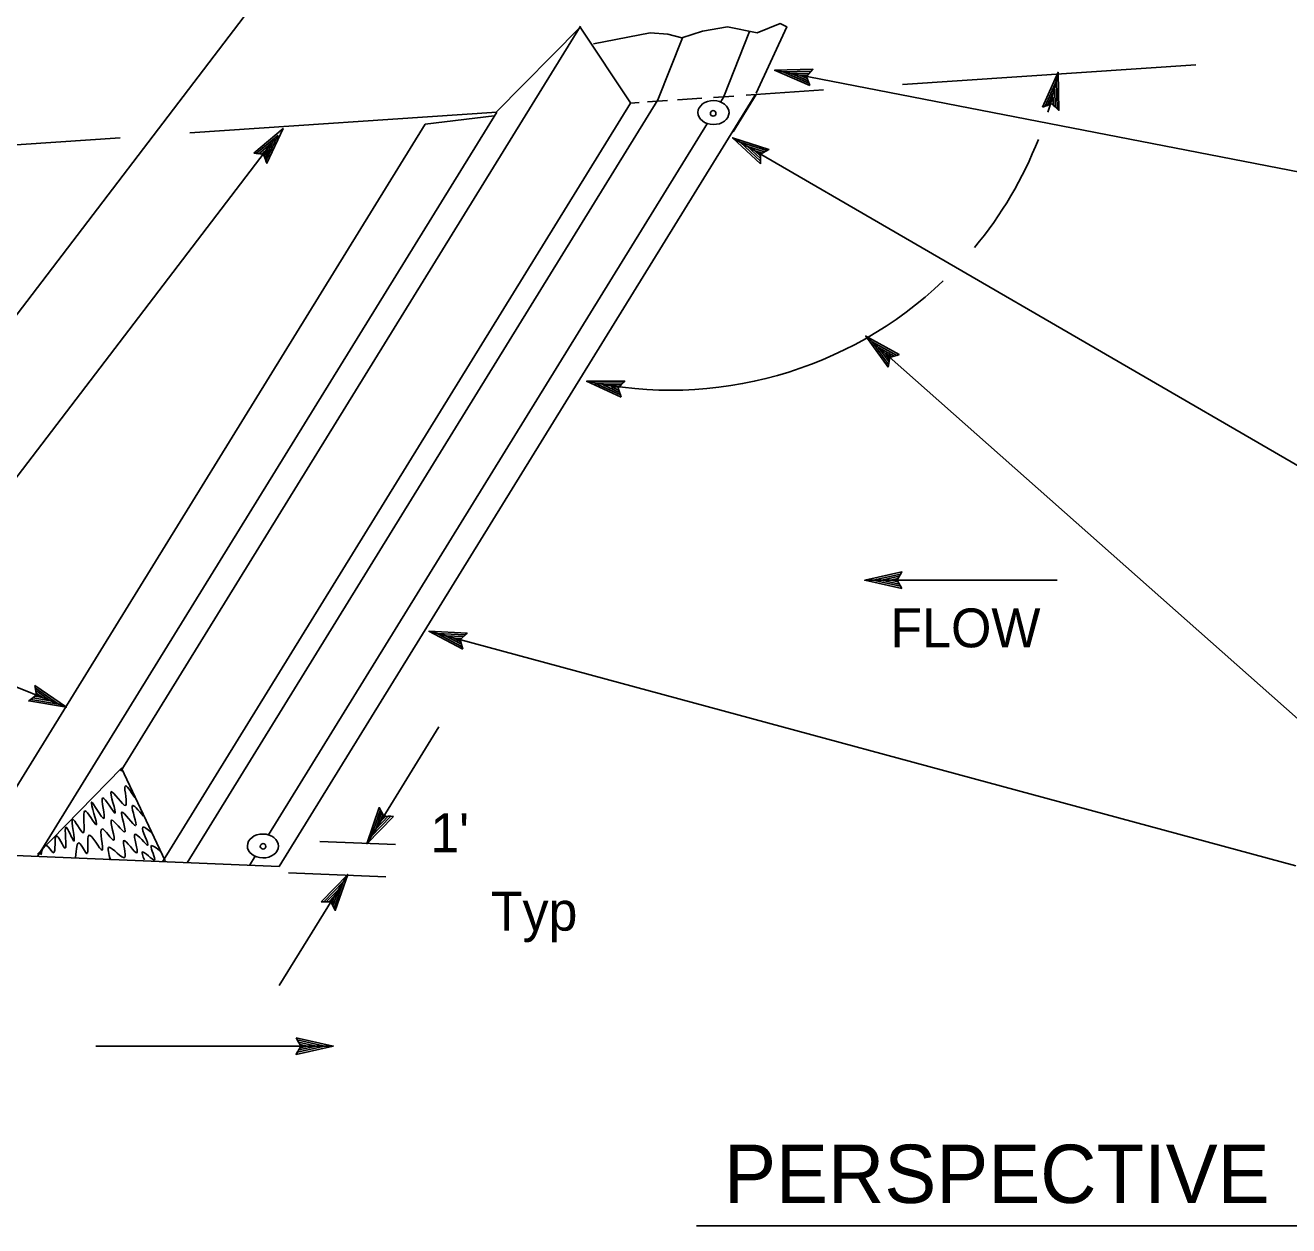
# Model space of a CAD drawing. Extents: x 6708945 to 6710368, y 1871409 to 1872338.
# Drawn here: x 6709648 to 6709843.2, y 1871758.9 to 1871944.4 of the extents above; entities that cross this region are included whole.
import ezdxf

# ---------------------------------------------------------------- set-up
doc = ezdxf.new("R2010")
doc.units = 0
doc.layers.add('57 Undefined', color=7, linetype='Continuous')
doc.layers.add('60 Nongeo Data', color=7, linetype='Continuous')

msp = doc.modelspace()

# ---------------------------------------------------------------- linework, layer by layer
at = {"layer": '57 Undefined'}
for p, q in [((6709642.88, 1871894.69), (6709692.17, 1871959.27)), ((6709763.76, 1871937.4), (6709845.14, 1871921.6)), ((6709646.09, 1871873.81), (6709686.54, 1871926.81)), ((6709757.25, 1871926.98), (6709845.14, 1871876)), ((6709777.83, 1871896.35), (6709846.44, 1871835.61)), ((6709777.67, 1871858.65), (6709807.39, 1871858.65)), ((6709626.36, 1871850.36), (6709654.36, 1871839.02)), ((6709710.36, 1871850.75), (6709844.26, 1871814.52)), ((6709700.75, 1871817.95), (6709711.89, 1871836.01)), ((6709687.23, 1871796.04), (6709697.83, 1871813.21)), ((6709695.59, 1871786.69), (6709658.88, 1871786.69)), ((6709751.68, 1871758.94), (6709848.82, 1871758.94))]:
    msp.add_line(p, q, dxfattribs=at)
for points in [[(6709693.49, 1871818.31), (6709705.21, 1871817.82)], [(6709688.65, 1871813.47), (6709703.71, 1871812.85)]]:
    msp.add_lwpolyline(points, dxfattribs=at)
for start, end in [(342.7521, 348.7024), (320.2883, 338.553), (257.7557, 313.6577)]:
    msp.add_arc((6709747.65, 1871949.07), 61.08, start, end, dxfattribs=at)
at = {"layer": '60 Nongeo Data'}
for p, q in [((6709662.75, 1871829.15), (6709733.77, 1871944.23)), ((6709745.71, 1871932.83), (6709749.51, 1871942.44)), ((6709755.93, 1871933.37), (6709759.89, 1871943.38)), ((6709763.76, 1871937.4), (6709763.76, 1871937.4)), ((6709769.66, 1871937.56), (6709769.66, 1871937.56)), ((6709807.55, 1871937.1), (6709807.55, 1871937.1)), ((6709769.17, 1871935.04), (6709769.17, 1871935.04)), ((6709669.18, 1871815.17), (6709741.49, 1871932.34)), ((6709672.99, 1871815.01), (6709745.71, 1871932.83)), ((6709687.23, 1871814.41), (6709760.72, 1871933.5)), ((6709755.42, 1871932.5), (6709755.92, 1871933.32)), ((6709757.34, 1871927.92), (6709760.88, 1871933.66)), ((6709649.88, 1871815.97), (6709720.83, 1871930.94)), ((6709709.77, 1871929.07), (6709720.41, 1871930.37)), ((6709805.16, 1871931.71), (6709805.16, 1871931.71)), ((6709807.68, 1871931.2), (6709807.68, 1871931.2)), ((6709640.23, 1871816.37), (6709709.77, 1871929.07)), ((6709685.57, 1871819.32), (6709753.41, 1871929.25)), ((6709687.82, 1871928.41), (6709687.82, 1871928.41)), ((6709757.25, 1871926.98), (6709757.25, 1871926.98)), ((6709683.3, 1871924.61), (6709683.3, 1871924.61)), ((6709762.88, 1871925.19), (6709762.88, 1871925.19)), ((6709685.34, 1871923.05), (6709685.34, 1871923.05)), ((6709761.59, 1871922.97), (6709761.59, 1871922.97)), ((6709777.83, 1871896.35), (6709777.83, 1871896.35)), ((6709782.99, 1871893.49), (6709782.99, 1871893.49)), ((6709781.29, 1871891.57), (6709781.29, 1871891.57)), ((6709734.7, 1871889.37), (6709734.7, 1871889.37)), ((6709740.6, 1871889.4), (6709740.6, 1871889.4)), ((6709740.05, 1871886.9), (6709740.05, 1871886.9)), ((6709783.43, 1871859.93), (6709783.43, 1871859.93)), ((6709777.67, 1871858.65), (6709777.67, 1871858.65)), ((6709783.43, 1871857.37), (6709783.43, 1871857.37)), ((6709710.36, 1871850.75), (6709710.36, 1871850.75)), ((6709716.26, 1871850.48), (6709716.26, 1871850.48)), ((6709715.59, 1871848), (6709715.59, 1871848)), ((6709649.5, 1871842.38), (6709649.5, 1871842.38)), ((6709648.54, 1871840), (6709648.54, 1871840)), ((6709654.36, 1871839.02), (6709654.36, 1871839.02)), ((6709702.69, 1871823.52), (6709702.69, 1871823.52)), ((6709704.87, 1871822.17), (6709704.87, 1871822.17)), ((6709700.75, 1871817.95), (6709700.75, 1871817.95)), ((6709682.66, 1871814.6), (6709683.53, 1871816.02)), ((6709697.83, 1871813.21), (6709697.83, 1871813.21)), ((6709693.71, 1871808.98), (6709693.71, 1871808.98)), ((6709695.89, 1871807.64), (6709695.89, 1871807.64)), ((6709689.83, 1871787.98), (6709689.83, 1871787.98)), ((6709695.59, 1871786.69), (6709695.59, 1871786.69)), ((6709689.83, 1871785.42), (6709689.83, 1871785.42))]:
    msp.add_line(p, q, dxfattribs=at)
for points in [[(6709720.68, 1871930.86), (6709733.7, 1871944.08), (6709741.48, 1871932.4)], [(6709735.78, 1871941.5), (6709744.54, 1871943.18), (6709747.24, 1871942.97), (6709749.4, 1871942.44), (6709752.63, 1871943.46), (6709756.46, 1871944.11), (6709761.04, 1871943.21), (6709764.6, 1871944.61), (6709765.62, 1871944.13), (6709760.91, 1871933.87)], [(6709783.5, 1871935.19), (6709828.82, 1871938.27)], [(6709759.35, 1871933.55), (6709771.31, 1871934.36)], [(6709741.49, 1871932.34), (6709742.82, 1871932.43)], [(6709744.14, 1871932.52), (6709747.22, 1871932.73)], [(6709748.76, 1871932.83), (6709752.52, 1871933.09)], [(6709754.3, 1871933.21), (6709757.48, 1871933.43)], [(6709673.41, 1871927.72), (6709720.83, 1871930.94)], [(6709628.22, 1871924.65), (6709662.68, 1871926.99)], [(6709649.92, 1871816.31), (6709662.86, 1871829.62), (6709669.63, 1871815.28)], [(6709640.23, 1871816.37), (6709687.23, 1871814.41)]]:
    msp.add_lwpolyline(points, dxfattribs=at)
for points in [[(6709769.17, 1871935.04), (6709763.76, 1871937.4), (6709769.66, 1871937.56), (6709769.4, 1871937.26), (6709765.08, 1871937.15), (6709769.04, 1871935.41), (6709768.9, 1871935.79), (6709766.37, 1871936.89), (6709769.13, 1871936.97), (6709768.86, 1871936.67), (6709767.67, 1871936.64), (6709768.77, 1871936.16), (6709768.66, 1871936.45), (6709769.66, 1871937.56), (6709768.66, 1871936.45)], [(6709805.16, 1871931.71), (6709807.55, 1871937.1), (6709807.68, 1871931.2), (6709807.38, 1871931.47), (6709807.29, 1871935.79), (6709805.54, 1871931.84), (6709805.91, 1871931.97), (6709807.03, 1871934.5), (6709807.09, 1871931.74), (6709806.8, 1871932.01), (6709806.77, 1871933.2), (6709806.28, 1871932.1), (6709806.57, 1871932.21), (6709807.68, 1871931.2), (6709806.57, 1871932.21)], [(6709683.3, 1871924.61), (6709687.82, 1871928.41), (6709685.34, 1871923.05), (6709685.19, 1871923.42), (6709687.01, 1871927.34), (6709683.69, 1871924.56), (6709684.09, 1871924.52), (6709686.21, 1871926.3), (6709685.04, 1871923.79), (6709684.9, 1871924.16), (6709685.4, 1871925.24), (6709684.48, 1871924.47), (6709684.79, 1871924.44), (6709685.34, 1871923.05), (6709684.79, 1871924.44)], [(6709761.59, 1871922.97), (6709757.25, 1871926.98), (6709762.88, 1871925.19), (6709762.53, 1871925), (6709758.41, 1871926.31), (6709761.58, 1871923.37), (6709761.58, 1871923.77), (6709759.55, 1871925.64), (6709762.18, 1871924.81), (6709761.83, 1871924.62), (6709760.69, 1871924.98), (6709761.57, 1871924.16), (6709761.57, 1871924.47), (6709762.88, 1871925.19), (6709761.57, 1871924.47)], [(6709781.29, 1871891.57), (6709777.83, 1871896.35), (6709782.99, 1871893.49), (6709782.61, 1871893.37), (6709778.83, 1871895.47), (6709781.36, 1871891.96), (6709781.44, 1871892.35), (6709779.82, 1871894.59), (6709782.23, 1871893.25), (6709781.85, 1871893.13), (6709780.81, 1871893.71), (6709781.51, 1871892.74), (6709781.57, 1871893.05), (6709782.99, 1871893.49), (6709781.57, 1871893.05)], [(6709740.05, 1871886.9), (6709734.7, 1871889.37), (6709740.6, 1871889.4), (6709740.32, 1871889.11), (6709736, 1871889.09), (6709739.93, 1871887.27), (6709739.8, 1871887.65), (6709737.29, 1871888.81), (6709740.05, 1871888.82), (6709739.78, 1871888.53), (6709738.58, 1871888.53), (6709739.67, 1871888.02), (6709739.58, 1871888.32), (6709740.6, 1871889.4), (6709739.58, 1871888.32)], [(6709783.43, 1871857.37), (6709777.67, 1871858.65), (6709783.43, 1871859.93), (6709783.22, 1871859.59), (6709779, 1871858.66), (6709783.22, 1871857.71), (6709783.02, 1871858.05), (6709780.32, 1871858.65), (6709783.02, 1871859.25), (6709782.81, 1871858.91), (6709781.65, 1871858.65), (6709782.82, 1871858.39), (6709782.66, 1871858.65), (6709783.43, 1871859.93), (6709782.66, 1871858.65)], [(6709715.59, 1871848), (6709710.36, 1871850.75), (6709716.26, 1871850.48), (6709715.97, 1871850.2), (6709711.65, 1871850.4), (6709715.48, 1871848.38), (6709715.37, 1871848.77), (6709712.92, 1871850.05), (6709715.68, 1871849.93), (6709715.4, 1871849.65), (6709714.2, 1871849.71), (6709715.27, 1871849.15), (6709715.18, 1871849.44), (6709716.26, 1871850.48), (6709715.18, 1871849.44)], [(6709649.5, 1871842.38), (6709654.36, 1871839.02), (6709648.54, 1871840), (6709648.86, 1871840.24), (6709653.12, 1871839.52), (6709649.56, 1871841.98), (6709649.62, 1871841.59), (6709651.9, 1871840.02), (6709649.18, 1871840.48), (6709649.49, 1871840.72), (6709650.67, 1871840.52), (6709649.68, 1871841.2), (6709649.73, 1871840.89), (6709648.54, 1871840), (6709649.73, 1871840.89)], [(6709704.87, 1871822.17), (6709700.75, 1871817.95), (6709702.69, 1871823.52), (6709702.87, 1871823.17), (6709701.45, 1871819.08), (6709704.47, 1871822.18), (6709704.08, 1871822.18), (6709702.14, 1871820.2), (6709703.05, 1871822.81), (6709703.23, 1871822.46), (6709702.84, 1871821.33), (6709703.68, 1871822.19), (6709703.37, 1871822.19), (6709702.69, 1871823.52), (6709703.37, 1871822.19)], [(6709693.71, 1871808.98), (6709697.83, 1871813.21), (6709695.89, 1871807.64), (6709695.71, 1871807.99), (6709697.13, 1871812.07), (6709694.1, 1871808.98), (6709694.5, 1871808.97), (6709696.43, 1871810.95), (6709695.52, 1871808.34), (6709695.34, 1871808.7), (6709695.73, 1871809.83), (6709694.9, 1871808.97), (6709695.2, 1871808.96), (6709695.89, 1871807.64), (6709695.2, 1871808.96)], [(6709689.83, 1871787.98), (6709695.59, 1871786.69), (6709689.83, 1871785.41), (6709690.03, 1871785.76), (6709694.25, 1871786.69), (6709690.03, 1871787.64), (6709690.23, 1871787.3), (6709692.93, 1871786.69), (6709690.24, 1871786.1), (6709690.44, 1871786.44), (6709691.61, 1871786.7), (6709690.44, 1871786.96), (6709690.59, 1871786.69), (6709689.83, 1871785.41), (6709690.59, 1871786.69)]]:
    msp.add_lwpolyline(points, close=True, dxfattribs=at)
for centre in [(6709754.27, 1871930.74), (6709684.74, 1871817.54)]:
    msp.add_circle(centre, 0.43, dxfattribs=at)
for centre in [(6709754.31, 1871930.87), (6709684.71, 1871817.6)]:
    msp.add_ellipse(centre, major_axis=(2.4, -0.03), ratio=0.768854, dxfattribs=at)
for points in [[(6709650.4, 1871816.23), (6709651.25, 1871817.71), (6709652.35, 1871816.55), (6709652.8, 1871819.2), (6709654.16, 1871817.26), (6709654.29, 1871820.49), (6709655.52, 1871818.36), (6709655.33, 1871821.72), (6709656.95, 1871819.65), (6709657.21, 1871823.02), (6709658.96, 1871820.88), (6709658.24, 1871824.37), (6709660.12, 1871821.85), (6709659.99, 1871825.02), (6709661.87, 1871822.69), (6709661.29, 1871825.99), (6709663.49, 1871823.86), (6709663.43, 1871826.83), (6709664.92, 1871825.09)], [(6709655.78, 1871815.84), (6709656.36, 1871818.04), (6709657.53, 1871816.42), (6709657.85, 1871819.27), (6709659.86, 1871816.94), (6709659.86, 1871820.24), (6709661.68, 1871818.49), (6709661.35, 1871821.59), (6709663.36, 1871819.78), (6709662.91, 1871822.82), (6709665.05, 1871820.75), (6709664.53, 1871823.79), (6709666.28, 1871822.18)], [(6709661.16, 1871815.39), (6709660.96, 1871817.39), (6709663.36, 1871815.84), (6709663.23, 1871818.43), (6709665.24, 1871816.55), (6709664.98, 1871819.4), (6709666.93, 1871817.71), (6709666.15, 1871820.49), (6709667.44, 1871819.72)], [(6709666.41, 1871815.45), (6709666.08, 1871816.68), (6709667.96, 1871815.45), (6709667.44, 1871817.58), (6709669, 1871816.68)]]:
    msp.add_spline(points, degree=3, dxfattribs=at)

# ---------------------------------------------------------------- texts
at = {"layer": '57 Undefined'}
for s, height, p in [('FLOW', 6, (6709781.64, 1871848.28)), ("1'", 6, (6709710.56, 1871816.62)), ('Typ', 6, (6709719.92, 1871804.52)), ('PERSPECTIVE', 9, (6709755.95, 1871762.46))]:
    msp.add_text(s, height=height, dxfattribs=at).set_placement(p)

doc.saveas('drawing.dxf')
